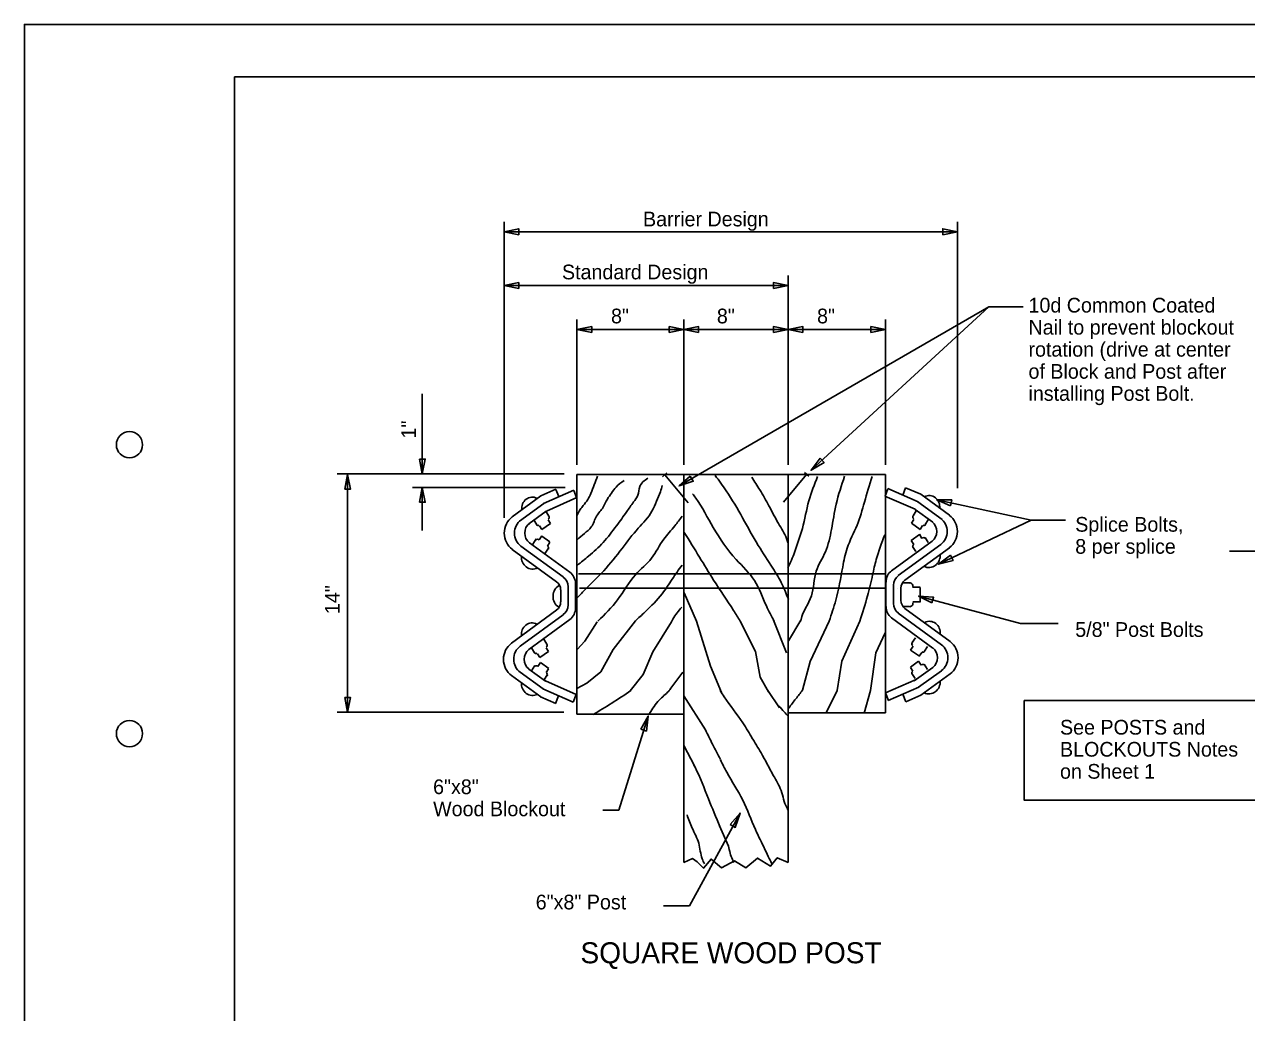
# Model space of a CAD drawing. Extents: x 0 to 34, y 0 to 22.
# Drawn here: x 0 to 11.64, y 12.6 to 22 of the extents above; entities that cross this region are included whole.
import ezdxf

# ---------------------------------------------------------------- set-up
doc = ezdxf.new("R2010")
doc.units = 0
for name, color, linetype in [('SH_Border', 7, 'Continuous'), ('SH_Cut_Line', 7, 'Continuous'), ('ST_Details', 7, 'Continuous'), ('ST_Text', 7, 'Continuous')]:
    doc.layers.add(name, color=color, linetype=linetype)

msp = doc.modelspace()

# ---------------------------------------------------------------- linework, layer by layer
at = {"layer": 'SH_Border'}
msp.add_lwpolyline([(2, 21.5), (33.5, 21.5), (33.5, 0.5), (2, 0.5)], close=True, dxfattribs=at)
for centre in [(1, 18), (1, 15.25)]:
    msp.add_circle(centre, 0.125, dxfattribs=at)
at = {"layer": 'SH_Cut_Line'}
msp.add_lwpolyline([(0, 0), (34, 0), (34, 22), (0, 22)], close=True, dxfattribs=at)
at = {"layer": 'ST_Details'}
for p, q in [((5.261, 17.716), (8.2, 17.716)), ((5.261, 17.716), (5.261, 15.435)), ((6.117, 17.731), (6.076, 17.694)), ((6.099, 17.712), (6.32, 17.447)), ((6.279, 17.716), (6.279, 14.022)), ((7.446, 17.717), (7.226, 17.452)), ((7.271, 17.716), (7.271, 14.022)), ((7.428, 17.736), (7.469, 17.699)), ((8.2, 17.716), (8.2, 15.448)), ((4.916, 17.513), (5.06, 17.576)), ((5.088, 17.506), (5.061, 17.575)), ((8.194, 17.511), (8.221, 17.581)), ((8.51, 17.455), (8.22, 17.582)), ((8.363, 17.521), (8.39, 17.59)), ((8.534, 17.528), (8.39, 17.591)), ((4.917, 17.513), (4.644, 17.313)), ((4.941, 17.44), (5.231, 17.566)), ((4.97, 17.369), (5.26, 17.496)), ((5.257, 17.496), (5.23, 17.565)), ((8.48, 17.385), (8.191, 17.511)), ((8.507, 17.457), (8.737, 17.288)), ((8.534, 17.528), (8.807, 17.328)), ((4.944, 17.441), (4.714, 17.273)), ((4.969, 17.369), (4.803, 17.247)), ((4.994, 17.321), (4.964, 17.368)), ((8.461, 17.323), (8.491, 17.37)), ((8.481, 17.384), (8.648, 17.262)), ((4.878, 17.238), (4.849, 17.284)), ((4.927, 17.192), (4.904, 17.228)), ((4.927, 17.192), (5.009, 17.251)), ((5.009, 17.251), (4.986, 17.286)), ((8.446, 17.253), (8.468, 17.288)), ((8.528, 17.194), (8.446, 17.253)), ((8.528, 17.194), (8.551, 17.23)), ((8.577, 17.24), (8.606, 17.286)), ((4.901, 17.093), (4.926, 17.132)), ((5.004, 17.074), (4.925, 17.131)), ((8.443, 17.089), (8.522, 17.146)), ((8.546, 17.108), (8.522, 17.147)), ((8.606, 17.068), (8.575, 17.118)), ((5.067, 16.696), (4.644, 17.004)), ((5.131, 16.741), (4.727, 17.035)), ((5.194, 16.786), (4.809, 17.066)), ((4.841, 17.053), (4.873, 17.103)), ((4.959, 16.967), (4.99, 17.015)), ((4.98, 17.035), (5.004, 17.073)), ((8.257, 16.801), (8.642, 17.081)), ((8.32, 16.756), (8.724, 17.05)), ((8.383, 16.711), (8.807, 17.019)), ((8.468, 17.051), (8.444, 17.088)), ((8.488, 16.982), (8.457, 17.03)), ((5.276, 16.77), (8.201, 16.77)), ((5.176, 16.475), (5.176, 16.648)), ((5.247, 16.445), (5.247, 16.678)), ((8.203, 16.46), (8.203, 16.693)), ((8.274, 16.49), (8.274, 16.663)), ((8.361, 16.684), (8.433, 16.684)), ((8.456, 16.643), (8.529, 16.643)), ((8.529, 16.503), (8.529, 16.642)), ((5.106, 16.504), (5.106, 16.618)), ((5.176, 16.556), (5.176, 16.567)), ((5.284, 16.634), (8.197, 16.634)), ((6.282, 16.59), (6.399, 16.321)), ((8.274, 16.571), (8.274, 16.582)), ((8.317, 16.632), (8.317, 16.632)), ((8.345, 16.519), (8.345, 16.634)), ((5.068, 16.427), (4.637, 16.112)), ((8.362, 16.459), (8.424, 16.459)), ((8.383, 16.442), (8.814, 16.127)), ((8.459, 16.503), (8.533, 16.503)), ((5.131, 16.382), (4.72, 16.081)), ((5.194, 16.337), (4.802, 16.05)), ((7.133, 16.33), (7.256, 16.019)), ((7.393, 16.33), (7.274, 16.133)), ((8.257, 16.353), (8.649, 16.065)), ((8.32, 16.398), (8.731, 16.096)), ((4.858, 16.02), (4.829, 16.066)), ((4.974, 16.103), (4.944, 16.15)), ((4.989, 16.033), (4.967, 16.068)), ((8.438, 16.046), (8.461, 16.082)), ((8.453, 16.116), (8.484, 16.163)), ((8.569, 16.034), (8.598, 16.079)), ((4.907, 15.974), (4.884, 16.01)), ((4.907, 15.974), (4.989, 16.033)), ((8.521, 15.988), (8.438, 16.046)), ((8.52, 15.987), (8.544, 16.023)), ((4.938, 15.675), (4.72, 15.834)), ((4.96, 15.75), (4.802, 15.865)), ((4.829, 15.848), (4.86, 15.898)), ((4.889, 15.888), (4.913, 15.927)), ((4.992, 15.869), (4.913, 15.927)), ((4.968, 15.831), (4.991, 15.868)), ((6.146, 15.669), (6.269, 15.835)), ((8.436, 15.882), (8.514, 15.94)), ((8.46, 15.844), (8.436, 15.881)), ((8.473, 15.753), (8.648, 15.88)), ((8.513, 15.691), (8.731, 15.849)), ((8.539, 15.901), (8.514, 15.94)), ((8.599, 15.861), (8.567, 15.911)), ((4.917, 15.599), (4.638, 15.803)), ((4.947, 15.762), (4.978, 15.81)), ((4.96, 15.751), (5.254, 15.623)), ((5.259, 15.678), (5.354, 15.729)), ((8.491, 15.766), (8.197, 15.638)), ((8.481, 15.775), (8.45, 15.823)), ((8.534, 15.615), (8.813, 15.818)), ((4.915, 15.6), (5.059, 15.537)), ((5.226, 15.549), (4.936, 15.676)), ((5.058, 15.538), (5.086, 15.61)), ((5.225, 15.549), (5.253, 15.623)), ((6.485, 15.285), (6.278, 15.611)), ((7.077, 15.66), (7.188, 15.495)), ((7.634, 15.448), (7.739, 15.66)), ((7.994, 15.444), (8.057, 15.66)), ((8.226, 15.565), (8.197, 15.638)), ((8.225, 15.565), (8.515, 15.691)), ((8.393, 15.553), (8.365, 15.626)), ((8.536, 15.615), (8.392, 15.553)), ((5.261, 15.435), (6.278, 15.435)), ((7.27, 15.448), (8.199, 15.448)), ((6.278, 15.137), (6.379, 14.944)), ((6.619, 14.373), (6.703, 14.178))]:
    msp.add_line(p, q, dxfattribs=at)
for points in [[(5.453, 16.313), (5.335, 16.129), (5.264, 16.05)], [(5.819, 16.325), (5.607, 16.05), (5.488, 15.839), (5.354, 15.729)], [(6.16, 16.315), (5.984, 16.028), (5.892, 15.813), (5.768, 15.656)], [(6.399, 16.321), (6.532, 15.892), (6.637, 15.642)], [(6.816, 16.321), (6.962, 16.032), (7.006, 15.787), (7.086, 15.647)], [(7.662, 16.321), (7.48, 15.936), (7.409, 15.665)], [(7.955, 16.321), (7.783, 15.94), (7.739, 15.66)], [(8.057, 15.66), (8.107, 16.019), (8.195, 16.208)], [(6.279, 14.022), (6.36, 14.06), (6.406, 14.03), (6.464, 13.968), (6.538, 14.056), (6.638, 13.973), (6.762, 14.038), (6.869, 13.973), (6.981, 14.065), (7.105, 13.99), (7.167, 14.069), (7.271, 14.022)]]:
    msp.add_lwpolyline(points, dxfattribs=at)
for centre, major_axis, start_param, end_param in [((4.836, 17.394), (0, -0.107), 2.687211, 4.851441), ((8.614, 17.409), (0, -0.107), 1.431744, 3.595974), ((4.745, 17.159), (0, -0.187), 3.747084, 5.680264), ((4.807, 17.159), (0, -0.15), 3.747137, 5.680324), ((4.869, 17.159), (0, -0.112), 3.747102, 5.680297), ((4.891, 17.249), (0, -0.0195), 5.247458, 6.879592), ((4.978, 17.309), (0, 0.0198), 3.70437, 5.352473), ((8.477, 17.311), (0, 0.0198), 0.930712, 2.578815), ((8.564, 17.251), (0, -0.0195), 5.686779, 7.318912), ((8.582, 17.174), (0, -0.112), 0.602888, 2.536083), ((8.644, 17.174), (0, -0.15), 0.602861, 2.536048), ((8.706, 17.174), (0, -0.187), 0.602921, 2.536101), ((8.562, 17.095), (0, 0.021), 5.448045, 7.11407), ((4.885, 17.079), (0, 0.021), 5.452301, 7.118326), ((4.971, 17.017), (0, 0.021), 4.196406, 5.73538), ((8.477, 17.032), (0, 0.021), 0.547805, 2.086779), ((4.84, 16.931), (0, -0.115), 4.640651, 6.714317), ((8.611, 16.946), (0, -0.115), 5.852054, 7.925719), ((5.123, 16.678), (0, 0.131), 4.712389, 5.680267), ((8.327, 16.693), (0, 0.131), 0.602918, 1.570796), ((5.146, 16.556), (0, -0.12), 3.613765, 5.74142), ((5.017, 16.619), (0, 0.0937), 4.712389, 5.680377), ((5.07, 16.648), (0, 0.112), 4.712389, 5.68034), ((8.381, 16.663), (0, 0.112), 0.602846, 1.570796), ((8.434, 16.634), (0, 0.0937), 0.602808, 1.570796), ((8.431, 16.654), (0, -0.0298), 2.729343, 3.43401), ((8.43, 16.654), (0, 0.03), 4.574534, 6.237266), ((8.431, 16.654), (0, -0.0298), 1.431351, 1.439211), ((5.017, 16.504), (0, -0.0937), 0.605563, 1.570796), ((5.07, 16.475), (0, -0.112), 0.605651, 1.570796), ((5.123, 16.445), (0, -0.131), 0.605566, 1.570796), ((8.327, 16.46), (0, -0.131), 4.712389, 5.677619), ((8.381, 16.49), (0, -0.112), 4.712389, 5.677535), ((8.434, 16.519), (0, -0.0937), 4.712389, 5.677623), ((8.429, 16.491), (0, -0.0326), 6.093782, 8.000338), ((4.833, 16.197), (0, -0.107), 2.687211, 4.851441), ((8.618, 16.212), (0, -0.107), 1.431744, 3.595974), ((4.738, 15.957), (0, -0.187), 3.747091, 5.68028), ((4.8, 15.958), (0, -0.15), 3.747115, 5.680355), ((4.958, 16.091), (0, 0.0198), 3.70437, 5.352473), ((8.469, 16.104), (0, 0.0198), 0.930712, 2.578815), ((8.588, 15.973), (0, -0.112), 0.602927, 2.536083), ((8.651, 15.973), (0, -0.15), 0.602831, 2.53607), ((8.713, 15.973), (0, -0.187), 0.602905, 2.536094), ((4.863, 15.958), (0, -0.112), 3.747102, 5.680258), ((4.871, 16.031), (0, -0.0195), 5.247458, 6.879592), ((8.556, 16.044), (0, -0.0195), 5.686779, 7.318912), ((4.873, 15.875), (0, 0.021), 5.452301, 7.118326), ((4.959, 15.812), (0, 0.021), 4.196406, 5.73538), ((8.469, 15.825), (0, 0.021), 0.547805, 2.086779), ((8.555, 15.888), (0, 0.021), 5.448045, 7.11407), ((4.84, 15.728), (0, -0.115), 4.640651, 6.714317), ((8.611, 15.743), (0, -0.115), 5.852054, 7.925719)]:
    msp.add_ellipse(centre, major_axis=major_axis, ratio=0.944544, start_param=start_param, end_param=end_param, dxfattribs=at)
for points in [[(5.456, 17.702), (5.393, 17.536), (5.364, 17.478), (5.321, 17.42), (5.292, 17.382), (5.259, 17.324)], [(6.577, 17.707), (6.682, 17.561), (6.838, 17.303), (6.987, 17.042), (7.125, 16.826), (7.216, 16.669), (7.274, 16.526)], [(6.926, 17.69), (7.002, 17.569), (7.089, 17.419), (7.18, 17.249), (7.256, 17.107), (7.267, 17.069)], [(7.552, 17.698), (7.469, 17.466), (7.407, 17.203), (7.357, 17.05), (7.303, 16.901), (7.27, 16.831)], [(7.808, 17.7), (7.729, 17.435), (7.684, 17.194), (7.626, 16.98), (7.539, 16.796), (7.493, 16.56), (7.394, 16.337), (7.391, 16.321)], [(8.071, 17.698), (7.998, 17.453), (7.928, 17.234), (7.833, 17.015), (7.791, 16.836), (7.725, 16.52), (7.662, 16.321)], [(5.263, 16.851), (5.372, 16.94), (5.51, 17.07), (5.637, 17.228), (5.735, 17.363), (5.8, 17.455), (5.84, 17.52), (5.858, 17.601), (5.935, 17.682)], [(5.263, 17.094), (5.332, 17.155), (5.397, 17.217), (5.448, 17.32), (5.51, 17.405), (5.55, 17.482), (5.59, 17.54), (5.633, 17.597), (5.709, 17.658)], [(5.266, 16.547), (5.364, 16.647), (5.517, 16.801), (5.691, 17.013), (5.844, 17.205), (5.975, 17.367), (6.018, 17.463), (6.055, 17.551), (6.072, 17.613)], [(6.362, 17.533), (6.392, 17.492), (6.559, 17.211), (6.777, 16.907), (6.951, 16.707), (7.064, 16.465), (7.137, 16.321)], [(5.459, 16.321), (5.648, 16.524), (5.818, 16.763), (5.971, 16.92), (6.087, 17.101), (6.193, 17.228), (6.262, 17.32)], [(6.283, 17.165), (6.428, 16.93), (6.562, 16.711), (6.751, 16.423), (6.816, 16.321)], [(7.955, 16.321), (8.027, 16.56), (8.076, 16.761), (8.11, 16.906), (8.192, 17.142)], [(5.815, 16.321), (5.909, 16.409), (6.073, 16.582), (6.167, 16.72), (6.262, 16.855)], [(6.16, 16.315), (6.174, 16.34), (6.258, 16.455)], [(5.415, 15.432), (5.593, 15.54), (5.773, 15.66)], [(5.953, 15.443), (6.044, 15.57), (6.134, 15.655), (6.151, 15.675)], [(6.625, 15.66), (6.662, 15.601), (6.84, 15.352), (6.933, 15.199)], [(7.409, 15.665), (7.378, 15.623), (7.312, 15.54), (7.278, 15.492)], [(7.184, 15.515), (7.234, 15.457), (7.271, 15.415)], [(6.484, 15.287), (6.551, 15.15), (6.626, 15.003)], [(6.924, 15.214), (7.014, 15.067), (7.13, 14.853), (7.204, 14.708), (7.258, 14.546), (7.27, 14.524)], [(6.375, 14.951), (6.385, 14.931), (6.513, 14.629), (6.622, 14.365)], [(6.627, 15.001), (6.687, 14.883), (6.84, 14.616), (6.96, 14.336), (7.051, 14.148), (7.092, 14.06), (7.121, 14.003)], [(6.309, 14.478), (6.358, 14.351), (6.42, 14.207), (6.453, 14.058), (6.474, 14.01)], [(6.703, 14.178), (6.741, 14.051), (6.753, 14.025)]]:
    msp.add_spline(points, degree=3, dxfattribs=at)
at = {"layer": 'ST_Text'}
for p, q in [((4.567, 20.121), (4.567, 17.7)), ((4.567, 20.027), (7.282, 20.027)), ((7.282, 20.027), (8.884, 20.027)), ((8.884, 20.121), (8.884, 17.585)), ((7.272, 19.61), (7.272, 19.064)), ((7.272, 19.61), (7.272, 17.81)), ((4.567, 19.515), (6.666, 19.515)), ((6.666, 19.515), (7.272, 19.515)), ((7.49, 17.757), (9.181, 19.312)), ((9.181, 19.312), (9.508, 19.312)), ((5.261, 17.81), (5.261, 19.191)), ((8.2, 19.097), (5.261, 19.097)), ((6.279, 17.81), (6.279, 19.191)), ((8.2, 17.81), (8.2, 19.191)), ((3.788, 18.484), (3.788, 17.723)), ((2.978, 17.723), (5.139, 17.723)), ((3.077, 17.718), (3.077, 16.996)), ((4.567, 17.7), (4.567, 17.569)), ((3.694, 17.592), (5.149, 17.592)), ((3.788, 17.592), (3.788, 17.183)), ((4.567, 17.569), (4.567, 17.303)), ((8.687, 17.475), (9.587, 17.282)), ((8.704, 16.862), (9.587, 17.282)), ((9.587, 17.282), (9.912, 17.282)), ((3.077, 16.996), (3.077, 15.453)), ((8.514, 16.559), (9.485, 16.299)), ((9.841, 16.299), (9.485, 16.299)), ((2.978, 15.453), (5.135, 15.453)), ((5.939, 15.417), (5.659, 14.523)), ((5.659, 14.523), (5.507, 14.523)), ((6.332, 13.611), (6.814, 14.493)), ((6.332, 13.611), (6.085, 13.611))]:
    msp.add_line(p, q, dxfattribs=at)
for points in [[(4.707, 19.999), (4.567, 20.027), (4.707, 20.055)], [(8.744, 19.999), (8.884, 20.027), (8.744, 20.055)], [(4.707, 19.487), (4.567, 19.515), (4.707, 19.543)], [(7.132, 19.487), (7.272, 19.515), (7.132, 19.543)], [(5.401, 19.069), (5.261, 19.097), (5.401, 19.125)], [(6.139, 19.069), (6.279, 19.097), (6.139, 19.125)], [(6.419, 19.069), (6.279, 19.097), (6.419, 19.125)], [(7.132, 19.069), (7.272, 19.097), (7.132, 19.125)], [(7.412, 19.069), (7.272, 19.097), (7.412, 19.125)], [(8.06, 19.069), (8.2, 19.097), (8.06, 19.125)], [(3.76, 17.863), (3.788, 17.723), (3.816, 17.863)], [(7.575, 17.871), (7.49, 17.757), (7.613, 17.83)], [(3.049, 17.578), (3.077, 17.718), (3.105, 17.578)], [(6.34, 17.701), (6.233, 17.607), (6.368, 17.652)], [(3.76, 17.452), (3.788, 17.592), (3.816, 17.452)], [(8.818, 17.419), (8.687, 17.475), (8.829, 17.474)], [(8.818, 16.949), (8.704, 16.862), (8.842, 16.899)], [(8.641, 16.494), (8.514, 16.559), (8.656, 16.548)], [(3.049, 15.593), (3.077, 15.453), (3.105, 15.593)], [(9.52, 15.565), (12.305, 15.565), (12.305, 14.616), (9.52, 14.616)], [(5.869, 15.293), (5.939, 15.417), (5.922, 15.275)], [(6.719, 14.386), (6.814, 14.493), (6.768, 14.358)]]:
    msp.add_lwpolyline(points, close=True, dxfattribs=at)
for points in [[(6.233, 17.607), (9.181, 19.312)], [(13.304, 17.476), (11.724, 16.986), (11.473, 16.986)]]:
    msp.add_lwpolyline(points, dxfattribs=at)

# ---------------------------------------------------------------- texts
for s, rotation, p in [('Barrier Design', 360, (5.89, 20.078)), ('Standard Design', 360, (5.118, 19.574)), ('10d Common Coated', 360, (9.56, 19.258)), ('  8"', 360, (5.481, 19.155)), ('  8"', 360, (6.489, 19.155)), ('  8"', 360, (7.443, 19.155)), ('Nail to prevent blockout', 360, (9.56, 19.048)), ('rotation (drive at center', 360, (9.56, 18.838)), ('of Block and Post after', 360, (9.56, 18.628)), ('installing Post Bolt.', 360, (9.56, 18.418)), ('1"', 90, (3.729, 18.059)), ('Splice Bolts,', 360, (10.005, 17.172)), ('8 per splice', 360, (10.005, 16.962)), ('14" ', 90, (3.002, 16.388)), ('5/8" Post Bolts', 360, (10.005, 16.171)), ('See POSTS and', 360, (9.86, 15.241)), ('BLOCKOUTS Notes', 360, (9.86, 15.031)), ('on Sheet 1', 360, (9.86, 14.821)), ('6"x8"', 360, (3.891, 14.674)), ('Wood Blockout', 360, (3.891, 14.464)), ('6"x8" Post', 360, (4.868, 13.577))]:
    msp.add_text(s, height=0.14, rotation=rotation, dxfattribs=at).set_placement(p)
msp.add_text('SQUARE WOOD POST', height=0.2, dxfattribs=at).set_placement((5.294, 13.064))

doc.saveas('drawing.dxf')
